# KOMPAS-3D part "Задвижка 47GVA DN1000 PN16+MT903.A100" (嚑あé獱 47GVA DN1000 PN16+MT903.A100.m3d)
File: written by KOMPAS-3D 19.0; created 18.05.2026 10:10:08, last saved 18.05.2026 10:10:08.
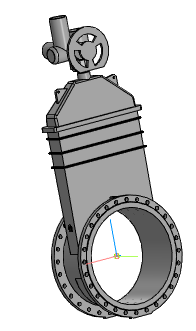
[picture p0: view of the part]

Document properties: Автор: Энергия; Полное имя файла: ..\Задвижка 47GVA DN40_DN1000+MT903.A\Задвижка 47GVA DN1000 PN16+MT903.A100.a3d

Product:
- Part/product: Задвижка 47GVA DN1000 PN16+MT903.A100
    Масса: 2909.57
  - Body: Электропривод МТ903.А100 без блока управления
      Масса: 346.451
  - Body: Задвижка 47GVA DN1000 PN16_F16 без исполнительного механизма
      Масса: 2563.12

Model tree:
1. Операция без истории:1
2. Операция без истории:2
